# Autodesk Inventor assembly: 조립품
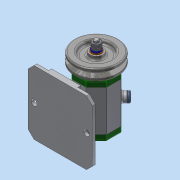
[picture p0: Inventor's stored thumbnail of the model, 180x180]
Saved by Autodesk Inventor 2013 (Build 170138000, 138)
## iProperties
Created: 2018-06
Part Number: 조립품
Document SubType Name: Assembly
Designer: dgall
Author: dgall
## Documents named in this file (16)
- C:\Users\dgall\Desktop\480607V1016\조립품.iam
- C:\Users\dgall\Desktop\480607V1016\V벨트풀리.ipt
- C:\Users\dgall\Desktop\480607V1016\고무캡.ipt
- C:\Users\dgall\Desktop\480607V1016\너트 M8.ipt
- 너트 M8.ipt
- C:\Users\dgall\Desktop\480607V1016\베어링 15x32x9.ipt
- C:\Users\dgall\Desktop\480607V1016\본체.ipt
- C:\Users\dgall\Desktop\480607V1016\볼트 M4x12.ipt
- C:\Users\dgall\Desktop\480607V1016\스프링와셔 8.ipt
- C:\Users\dgall\Desktop\480607V1016\앞커버.ipt
- C:\Users\dgall\Desktop\480607V1016\오일 실 15 25 7.ipt
- C:\Users\dgall\Desktop\480607V1016\와셔 8x17.ipt
- C:\Users\dgall\Desktop\480607V1016\축.ipt
- C:\Users\dgall\Desktop\480607V1016\키 3x3x12.ipt
- 키 3x3x12.ipt
- C:\Users\dgall\Desktop\480607V1016\뒤커버.ipt
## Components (2 placed, 2 different names)
1. V벨트풀리:1
2. 고무캡:1
